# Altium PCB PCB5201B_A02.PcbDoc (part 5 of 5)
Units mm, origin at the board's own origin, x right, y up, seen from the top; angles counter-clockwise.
Board outline 115 x 60 mm, 6 copper layers (Top Layer, GND Layer 2, Signal Layer 3, Signal Layer 4, VCC Layer 5, Bottom Layer), stack 1.555 mm thick; 355 components, 250 nets, 1223 pads, 1070 vias.
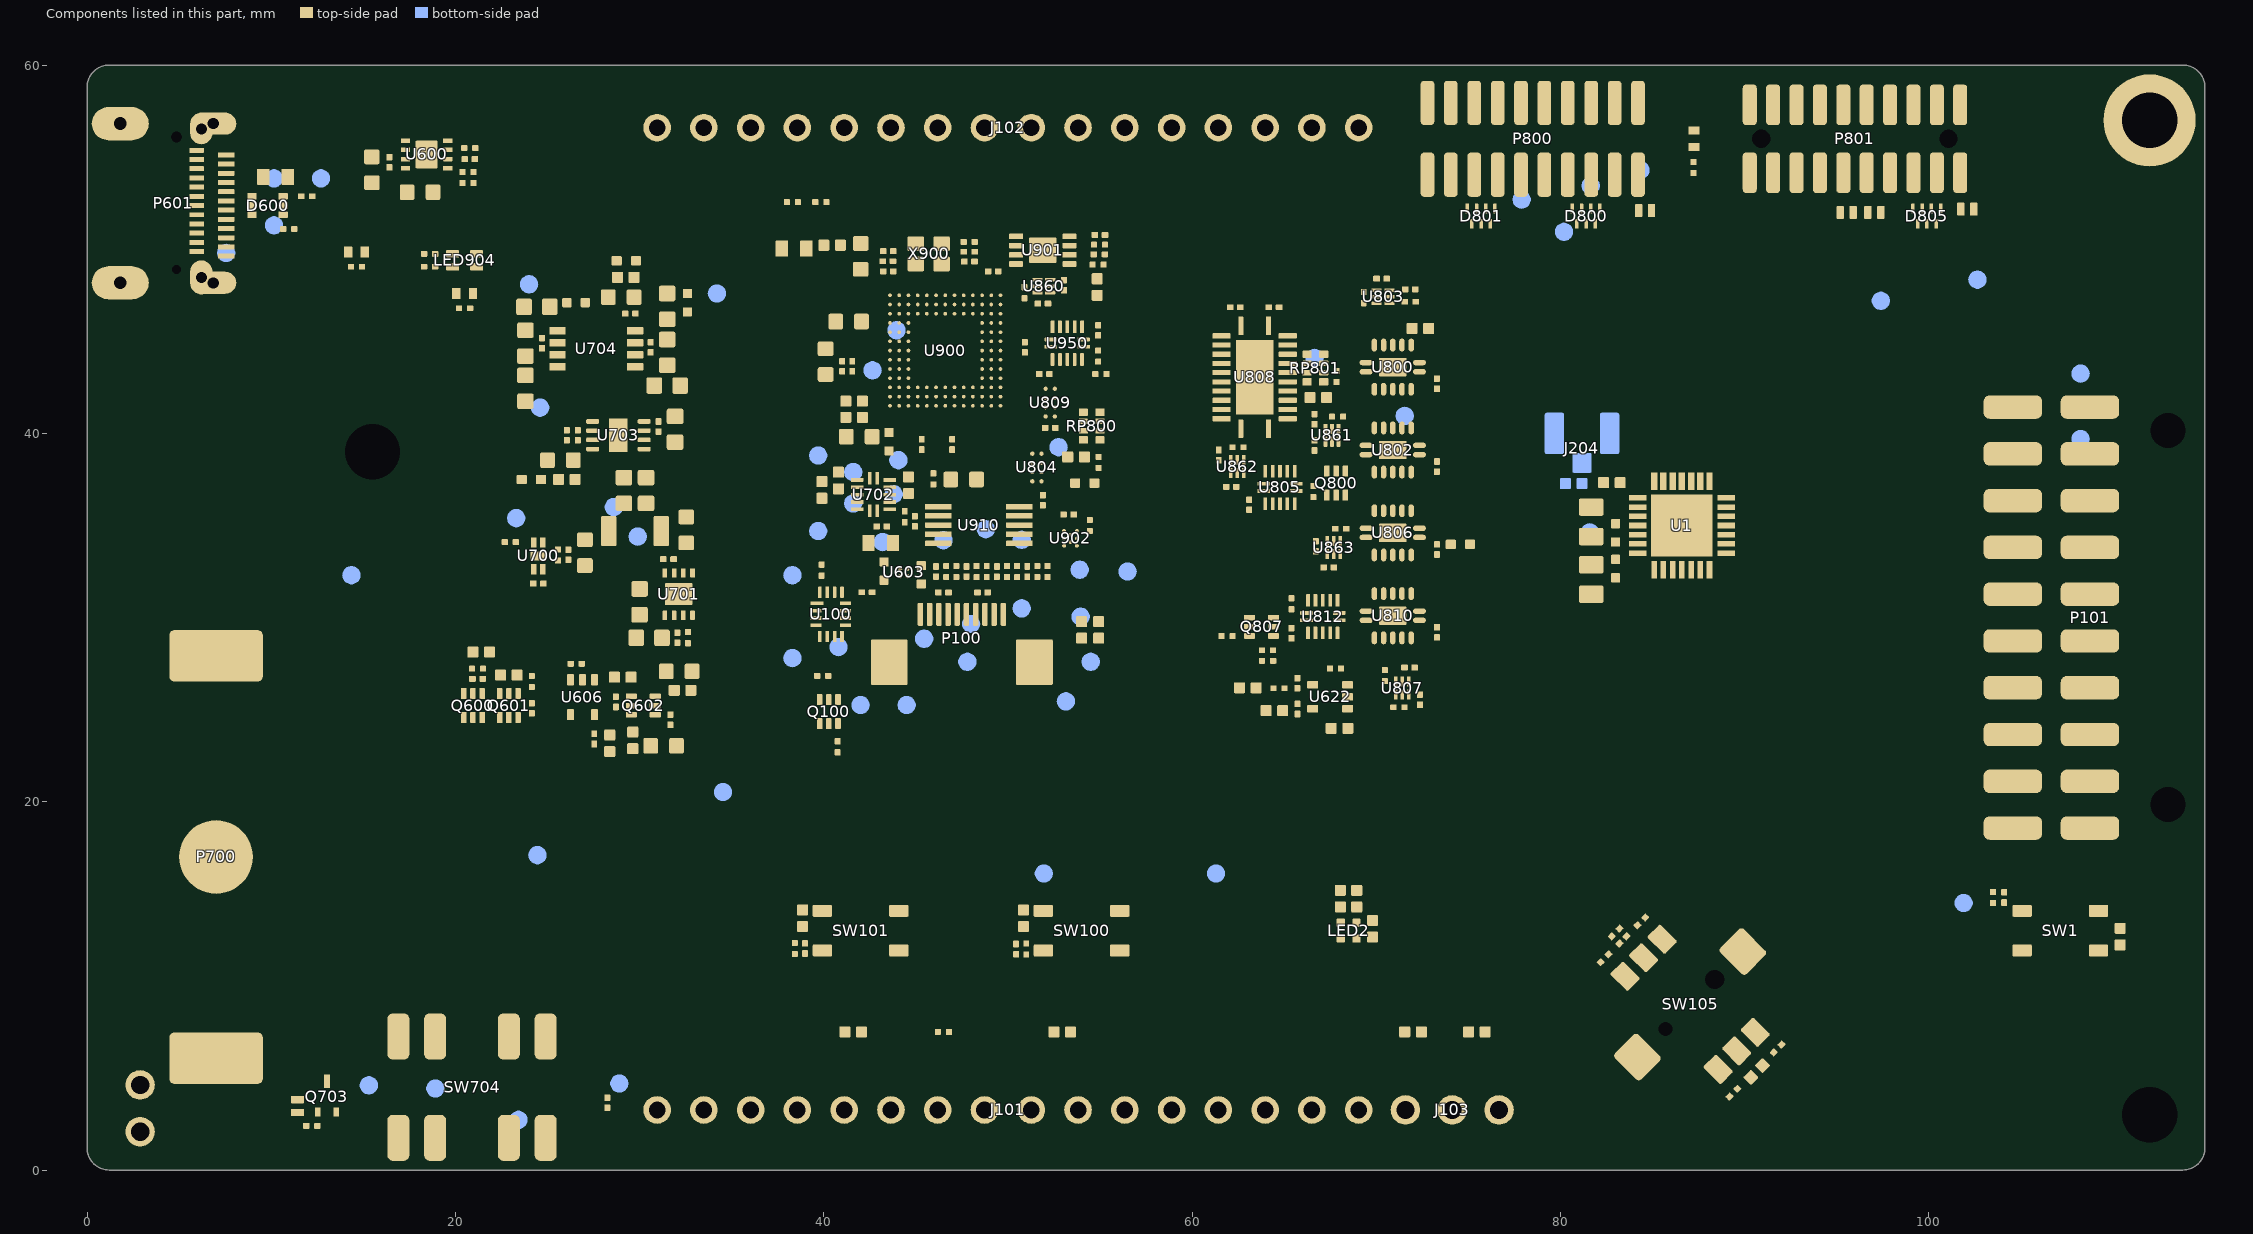
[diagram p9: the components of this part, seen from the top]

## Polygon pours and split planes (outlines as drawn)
VMCU on VCC Layer 5 "VMCU_L05_P027" (solid, remove dead copper, pour order 27): 77.925,39.7 78.35,40.125 101.725,40.125 102.45,40.85 102.45,59.275 103.175,60 115,60 115,0 21.05,0 21,0 20.275,0.725 20.275,6.3 20.525,6.55 29.025,6.55 29.55,7.075 29.55,23.225 30.05,23.725 77,23.725 77.925,24.65
3V3 on VCC Layer 5 "3V3_L05_P024" (solid, remove dead copper, pour order 24): 8.575,35.895 8.655,35.975 17.95,35.975 30.15,35.975 33.6,32.525 41.5,32.525 44.511,35.536 44.511,42.104 42.691,43.95 37.65,43.95 36.142,45.458 18.139,45.458 15.55,48.08 15.55,52.3 15.965,52.715 63.865,52.715 68.451,57.301 70.656,57.299 77.682,50.375 95.65,50.375 99.4,54.125 99.4,59.05 99.825,59.475 101.95,59.475 102.225,59.2 102.225,41.075 101.525,40.375 78.1,40.375 77.625,39.9 77.65,39.825 77.65,24.775 76.875,24 29.85,24 29.3,23.45 29.3,23.225 29.3,7.275 29.3,7.225 28.875,6.775 19.525,6.775 17.875,8.425 17.875,26.425 8.575,35.725
5V on VCC Layer 5 "5V_L05_P005" (solid, remove dead copper, pour order 5): 42.575,43.7 37.487,43.7 35.988,45.225 18.05,45.225 15.35,47.925 15.35,52.4 15.875,52.925 63.725,52.925 68.35,57.55 70.775,57.55 77.75,50.575 95.6,50.575 99.25,54.225 99.25,59.1 98.9,59.45 7.825,59.45 7.65,59.275 7.65,36.6 8.05,36.2 30.275,36.2 33.7,32.775 41.4,32.775 44.275,35.65 44.275,42
GND on VCC Layer 5 "VCC Layer 5-GND" (solid, remove dead copper, pour order 28): 0.5,0.5 19.25,0.5 19.5,0.75 19.5,5.775 17.1,8.175 17.1,26.175 7.1,36.175 7.1,59.5 0.95,59.5 0.5,59.05 0.5,35.4
GND on Top Layer "GND_L01_P021" (solid, remove dead copper, pour order 21): 0,0 0,60 125,60 125,0
USBC_VBUS on Top Layer "USBC_VBUS_L01_P020" (solid, remove dead copper, pour order 20): 9.85,55.125 9.85,53.575 8.825,53.575 8.4,54 8.4,54.725 9,55.325 9.717,55.325
5V on Top Layer "5V_L01_P019" (solid, remove dead copper, pour order 19): 10.6,53.525 10.6,55.075 11.075,55.55 11.925,55.55 12.275,55.2 12.275,53.65 12.25,53.65 12.125,53.525 10.675,53.525
5V on Top Layer "5V_L01_P018" (solid, remove dead copper, pour order 18): 14.375,54.625 13.975,55.025 13.975,56.175 14.325,56.525 16.375,56.525 16.8,56.1 16.8,55.225 16.45,54.875 15.725,54.875 15.725,54.7 15.65,54.625
3V3 on Top Layer "3V3_L01_P017" (solid, remove dead copper, pour order 17): 17.025,54.5 16.825,54.3 16.825,53.85 16.225,53.25 16.225,51.875 16.55,51.55 17.95,51.55 18.25,51.85 18.25,52.55 17.775,53.025 17.775,54.2 17.475,54.5
VMCU_R on Top Layer "VMCU_R_L01_P016" (solid, remove dead copper, pour order 16): 31.5,32.2 31.475,32.225 31.475,32.8 31.375,32.9 31.05,32.9 30.25,33.7 29.3,33.7 28.95,33.35 28.95,32.575 29.35,32.175 31.475,32.175 31.5,32.2 31.5,32.225
VMCU_R on Top Layer "VMCU_R_L01_P015" (solid, remove dead copper, pour order 15): 30.525,35.475 30.375,35.325 30.375,34.25 29.875,33.75 29.325,33.75 28.95,33.375 28.95,33.2 29.175,32.975 30.125,32.975 31.05,33.9 31.475,33.9 31.575,34 31.575,35.475
VMCU_S on Top Layer "VMCU_S_L01_P014" (solid, remove dead copper, pour order 14): 28.725,35.5 28.675,35.45 28.675,33.925 27.25,33.925 27.15,33.825 26.75,33.825 26.475,33.55 26.45,33.575 25.275,33.575 25.075,33.775 25.075,34.95 25.6,35.475 28.575,35.475 28.6,35.5
5V on Top Layer "5V_L01_P013" (solid, remove dead copper, pour order 13): 31.7,33.075 31.7,33.625 32.15,34.075 32.15,34.35 32.25,34.45 33.25,34.45 33.725,34.925 34.05,34.925 34.325,34.65 34.325,33.4 33.825,32.9 32.25,32.9 32.075,33.075
AEM_VMCU on Top Layer "AEM_VMCU_L01_P002" (solid, remove dead copper, pour order 2): 24.375,32.875 24.35,32.9 23.65,32.9 23.3,32.55 23.3,31.625 23.1,31.425 23.1,31 23.325,30.775 24.3,30.775 24.55,31.025 24.55,31.5 24.375,31.675
GND on Signal Layer 3 "GND_L03_P025" (solid, remove dead copper, pour order 25): 0,0 0,60 125,60 125,0
3V3 on Signal Layer 3 "3V3_L03_P022" (solid, remove dead copper, pour order 22): 18.15,51.675 18.525,52.05 18.525,54.175 17.7,55 17.7,56.85 17.225,57.325 16.3,57.325 15.925,56.95 15.925,55.125 16.525,54.525 16.525,51.775 16.625,51.675
GND on GND Layer 2 "GND_L02_P009" (solid, remove dead copper, pour order 9): 0,0 0,60 125,60 125,0
GND on Bottom Layer "GND_L06_P008" (solid, remove dead copper, pour order 8): 0,0 0,60 125,60 125,0
GND on Signal Layer 4 "GND_L04_P012" (solid, remove dead copper, pour order 12): 0,0 0,60 125,60 125,0

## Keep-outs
Bottom Layer:
  region: 12.7,54.35 cw(c12.7,53.85) 13.2,53.85 cw(c12.7,53.85) 12.7,53.35 cw(c12.7,53.85) 12.2,53.85 cw(c12.7,53.85)
  region: 32.691,5.802 ccw(c33.491,5.802) 33.491,5.002 ccw(c33.491,5.802) 34.291,5.802 ccw(c33.491,5.802) 33.491,6.602 ccw(c33.491,5.802)
  region: 35.231,5.802 ccw(c36.031,5.802) 36.031,5.002 ccw(c36.031,5.802) 36.831,5.802 ccw(c36.031,5.802) 36.031,6.602 ccw(c36.031,5.802)
  region: 37.771,5.802 ccw(c38.571,5.802) 38.571,5.002 ccw(c38.571,5.802) 39.371,5.802 ccw(c38.571,5.802) 38.571,6.602 ccw(c38.571,5.802)
  region: 40.311,5.802 ccw(c41.111,5.802) 41.111,5.002 ccw(c41.111,5.802) 41.911,5.802 ccw(c41.111,5.802) 41.111,6.602 ccw(c41.111,5.802)
  region: 42.851,5.802 ccw(c43.651,5.802) 43.651,5.002 ccw(c43.651,5.802) 44.451,5.802 ccw(c43.651,5.802) 43.651,6.602 ccw(c43.651,5.802)
  region: 45.391,5.802 ccw(c46.191,5.802) 46.191,5.002 ccw(c46.191,5.802) 46.991,5.802 ccw(c46.191,5.802) 46.191,6.602 ccw(c46.191,5.802)
  region: 47.931,5.802 ccw(c48.731,5.802) 48.731,5.002 ccw(c48.731,5.802) 49.531,5.802 ccw(c48.731,5.802) 48.731,6.602 ccw(c48.731,5.802)
  region: 50.471,5.802 ccw(c51.271,5.802) 51.271,5.002 ccw(c51.271,5.802) 52.071,5.802 ccw(c51.271,5.802) 51.271,6.602 ccw(c51.271,5.802)
  region: 53.011,5.802 ccw(c53.811,5.802) 53.811,5.002 ccw(c53.811,5.802) 54.611,5.802 ccw(c53.811,5.802) 53.811,6.602 ccw(c53.811,5.802)
  region: 55.551,5.802 ccw(c56.351,5.802) 56.351,5.002 ccw(c56.351,5.802) 57.151,5.802 ccw(c56.351,5.802) 56.351,6.602 ccw(c56.351,5.802)
  region: 58.091,5.802 ccw(c58.891,5.802) 58.891,5.002 ccw(c58.891,5.802) 59.691,5.802 ccw(c58.891,5.802) 58.891,6.602 ccw(c58.891,5.802)
  region: 60.631,5.802 ccw(c61.431,5.802) 61.431,5.002 ccw(c61.431,5.802) 62.231,5.802 ccw(c61.431,5.802) 61.431,6.602 ccw(c61.431,5.802)
  region: 63.171,5.802 ccw(c63.971,5.802) 63.971,5.002 ccw(c63.971,5.802) 64.771,5.802 ccw(c63.971,5.802) 63.971,6.602 ccw(c63.971,5.802)
  region: 65.711,5.802 ccw(c66.511,5.802) 66.511,5.002 ccw(c66.511,5.802) 67.311,5.802 ccw(c66.511,5.802) 66.511,6.602 ccw(c66.511,5.802)
  region: 68.251,5.802 ccw(c69.051,5.802) 69.051,5.002 ccw(c69.051,5.802) 69.851,5.802 ccw(c69.051,5.802) 69.051,6.602 ccw(c69.051,5.802)
  region: 30.151,5.802 ccw(c30.951,5.802) 30.951,5.002 ccw(c30.951,5.802) 31.751,5.802 ccw(c30.951,5.802) 30.951,6.602 ccw(c30.951,5.802)
  region: 30.151,3.262 ccw(c30.951,3.262) 30.951,2.462 ccw(c30.951,3.262) 31.751,3.262 ccw(c30.951,3.262) 30.951,4.062 ccw(c30.951,3.262)
  region: 30.151,3.262 ccw(c30.951,3.262) 30.951,2.462 ccw(c30.951,3.262) 31.751,3.262 ccw(c30.951,3.262) 30.951,4.062 ccw(c30.951,3.262)
  region: 32.691,3.262 ccw(c33.491,3.262) 33.491,2.462 ccw(c33.491,3.262) 34.291,3.262 ccw(c33.491,3.262) 33.491,4.062 ccw(c33.491,3.262)
  region: 35.231,3.262 ccw(c36.031,3.262) 36.031,2.462 ccw(c36.031,3.262) 36.831,3.262 ccw(c36.031,3.262) 36.031,4.062 ccw(c36.031,3.262)
  region: 37.771,3.262 ccw(c38.571,3.262) 38.571,2.462 ccw(c38.571,3.262) 39.371,3.262 ccw(c38.571,3.262) 38.571,4.062 ccw(c38.571,3.262)
  region: 40.311,3.262 ccw(c41.111,3.262) 41.111,2.462 ccw(c41.111,3.262) 41.911,3.262 ccw(c41.111,3.262) 41.111,4.062 ccw(c41.111,3.262)
  region: 42.851,3.262 ccw(c43.651,3.262) 43.651,2.462 ccw(c43.651,3.262) 44.451,3.262 ccw(c43.651,3.262) 43.651,4.062 ccw(c43.651,3.262)
  region: 45.391,3.262 ccw(c46.191,3.262) 46.191,2.462 ccw(c46.191,3.262) 46.991,3.262 ccw(c46.191,3.262) 46.191,4.062 ccw(c46.191,3.262)
  region: 47.881,3.287 ccw(c48.681,3.287) 48.681,2.487 ccw(c48.681,3.287) 49.481,3.287 ccw(c48.681,3.287) 48.681,4.087 ccw(c48.681,3.287)
  region: 50.471,3.262 ccw(c51.271,3.262) 51.271,2.462 ccw(c51.271,3.262) 52.071,3.262 ccw(c51.271,3.262) 51.271,4.062 ccw(c51.271,3.262)
  region: 53.011,3.262 ccw(c53.811,3.262) 53.811,2.462 ccw(c53.811,3.262) 54.611,3.262 ccw(c53.811,3.262) 53.811,4.062 ccw(c53.811,3.262)
  region: 55.551,3.262 ccw(c56.351,3.262) 56.351,2.462 ccw(c56.351,3.262) 57.151,3.262 ccw(c56.351,3.262) 56.351,4.062 ccw(c56.351,3.262)
  region: 58.091,3.262 ccw(c58.891,3.262) 58.891,2.462 ccw(c58.891,3.262) 59.691,3.262 ccw(c58.891,3.262) 58.891,4.062 ccw(c58.891,3.262)
  region: 60.631,3.262 ccw(c61.431,3.262) 61.431,2.462 ccw(c61.431,3.262) 62.231,3.262 ccw(c61.431,3.262) 61.431,4.062 ccw(c61.431,3.262)
  region: 63.171,3.262 ccw(c63.971,3.262) 63.971,2.462 ccw(c63.971,3.262) 64.771,3.262 ccw(c63.971,3.262) 63.971,4.062 ccw(c63.971,3.262)
  region: 65.711,3.262 ccw(c66.511,3.262) 66.511,2.462 ccw(c66.511,3.262) 67.311,3.262 ccw(c66.511,3.262) 66.511,4.062 ccw(c66.511,3.262)
  region: 68.251,3.262 ccw(c69.051,3.262) 69.051,2.462 ccw(c69.051,3.262) 69.851,3.262 ccw(c69.051,3.262) 69.051,4.062 ccw(c69.051,3.262)
  region: 32.691,56.602 ccw(c33.491,56.602) 33.491,55.802 ccw(c33.491,56.602) 34.291,56.602 ccw(c33.491,56.602) 33.491,57.402 ccw(c33.491,56.602)
  region: 35.231,56.602 ccw(c36.031,56.602) 36.031,55.802 ccw(c36.031,56.602) 36.831,56.602 ccw(c36.031,56.602) 36.031,57.402 ccw(c36.031,56.602)
  region: 37.771,56.602 ccw(c38.571,56.602) 38.571,55.802 ccw(c38.571,56.602) 39.371,56.602 ccw(c38.571,56.602) 38.571,57.402 ccw(c38.571,56.602)
  region: 40.311,56.602 ccw(c41.111,56.602) 41.111,55.802 ccw(c41.111,56.602) 41.911,56.602 ccw(c41.111,56.602) 41.111,57.402 ccw(c41.111,56.602)
  region: 42.851,56.602 ccw(c43.651,56.602) 43.651,55.802 ccw(c43.651,56.602) 44.451,56.602 ccw(c43.651,56.602) 43.651,57.402 ccw(c43.651,56.602)
  region: 45.391,56.602 ccw(c46.191,56.602) 46.191,55.802 ccw(c46.191,56.602) 46.991,56.602 ccw(c46.191,56.602) 46.191,57.402 ccw(c46.191,56.602)
  region: 47.931,56.602 ccw(c48.731,56.602) 48.731,55.802 ccw(c48.731,56.602) 49.531,56.602 ccw(c48.731,56.602) 48.731,57.402 ccw(c48.731,56.602)
  region: 50.471,56.602 ccw(c51.271,56.602) 51.271,55.802 ccw(c51.271,56.602) 52.071,56.602 ccw(c51.271,56.602) 51.271,57.402 ccw(c51.271,56.602)
  region: 53.011,56.602 ccw(c53.811,56.602) 53.811,55.802 ccw(c53.811,56.602) 54.611,56.602 ccw(c53.811,56.602) 53.811,57.402 ccw(c53.811,56.602)
  region: 55.551,56.602 ccw(c56.351,56.602) 56.351,55.802 ccw(c56.351,56.602) 57.151,56.602 ccw(c56.351,56.602) 56.351,57.402 ccw(c56.351,56.602)
  region: 58.091,56.602 ccw(c58.891,56.602) 58.891,55.802 ccw(c58.891,56.602) 59.691,56.602 ccw(c58.891,56.602) 58.891,57.402 ccw(c58.891,56.602)
  region: 60.631,56.602 ccw(c61.431,56.602) 61.431,55.802 ccw(c61.431,56.602) 62.231,56.602 ccw(c61.431,56.602) 61.431,57.402 ccw(c61.431,56.602)
  region: 63.171,56.602 ccw(c63.971,56.602) 63.971,55.802 ccw(c63.971,56.602) 64.771,56.602 ccw(c63.971,56.602) 63.971,57.402 ccw(c63.971,56.602)
  region: 65.711,56.602 ccw(c66.511,56.602) 66.511,55.802 ccw(c66.511,56.602) 67.311,56.602 ccw(c66.511,56.602) 66.511,57.402 ccw(c66.511,56.602)
  region: 68.251,56.602 ccw(c69.051,56.602) 69.051,55.802 ccw(c69.051,56.602) 69.851,56.602 ccw(c69.051,56.602) 69.051,57.402 ccw(c69.051,56.602)
  region: 30.151,56.602 ccw(c30.951,56.602) 30.951,55.802 ccw(c30.951,56.602) 31.751,56.602 ccw(c30.951,56.602) 30.951,57.402 ccw(c30.951,56.602)
  region: 30.151,54.062 ccw(c30.951,54.062) 30.951,53.262 ccw(c30.951,54.062) 31.751,54.062 ccw(c30.951,54.062) 30.951,54.862 ccw(c30.951,54.062)
  region: 30.151,54.062 ccw(c30.951,54.062) 30.951,53.262 ccw(c30.951,54.062) 31.751,54.062 ccw(c30.951,54.062) 30.951,54.862 ccw(c30.951,54.062)
  region: 32.691,54.062 ccw(c33.491,54.062) 33.491,53.262 ccw(c33.491,54.062) 34.291,54.062 ccw(c33.491,54.062) 33.491,54.862 ccw(c33.491,54.062)
  region: 35.231,54.062 ccw(c36.031,54.062) 36.031,53.262 ccw(c36.031,54.062) 36.831,54.062 ccw(c36.031,54.062) 36.031,54.862 ccw(c36.031,54.062)
  region: 37.771,54.062 ccw(c38.571,54.062) 38.571,53.262 ccw(c38.571,54.062) 39.371,54.062 ccw(c38.571,54.062) 38.571,54.862 ccw(c38.571,54.062)
  region: 40.311,54.062 ccw(c41.111,54.062) 41.111,53.262 ccw(c41.111,54.062) 41.911,54.062 ccw(c41.111,54.062) 41.111,54.862 ccw(c41.111,54.062)
  region: 42.851,54.062 ccw(c43.651,54.062) 43.651,53.262 ccw(c43.651,54.062) 44.451,54.062 ccw(c43.651,54.062) 43.651,54.862 ccw(c43.651,54.062)
  region: 45.391,54.062 ccw(c46.191,54.062) 46.191,53.262 ccw(c46.191,54.062) 46.991,54.062 ccw(c46.191,54.062) 46.191,54.862 ccw(c46.191,54.062)
  region: 47.931,54.062 ccw(c48.731,54.062) 48.731,53.262 ccw(c48.731,54.062) 49.531,54.062 ccw(c48.731,54.062) 48.731,54.862 ccw(c48.731,54.062)
  region: 50.471,54.062 ccw(c51.271,54.062) 51.271,53.262 ccw(c51.271,54.062) 52.071,54.062 ccw(c51.271,54.062) 51.271,54.862 ccw(c51.271,54.062)
  region: 53.011,54.062 ccw(c53.811,54.062) 53.811,53.262 ccw(c53.811,54.062) 54.611,54.062 ccw(c53.811,54.062) 53.811,54.862 ccw(c53.811,54.062)
  region: 55.551,54.062 ccw(c56.351,54.062) 56.351,53.262 ccw(c56.351,54.062) 57.151,54.062 ccw(c56.351,54.062) 56.351,54.862 ccw(c56.351,54.062)
  region: 58.091,54.062 ccw(c58.891,54.062) 58.891,53.262 ccw(c58.891,54.062) 59.691,54.062 ccw(c58.891,54.062) 58.891,54.862 ccw(c58.891,54.062)
  region: 60.631,54.062 ccw(c61.431,54.062) 61.431,53.262 ccw(c61.431,54.062) 62.231,54.062 ccw(c61.431,54.062) 61.431,54.862 ccw(c61.431,54.062)
  region: 63.171,54.062 ccw(c63.971,54.062) 63.971,53.262 ccw(c63.971,54.062) 64.771,54.062 ccw(c63.971,54.062) 63.971,54.862 ccw(c63.971,54.062)
  region: 65.711,54.062 ccw(c66.511,54.062) 66.511,53.262 ccw(c66.511,54.062) 67.311,54.062 ccw(c66.511,54.062) 66.511,54.862 ccw(c66.511,54.062)
  region: 68.251,54.062 ccw(c69.051,54.062) 69.051,53.262 ccw(c69.051,54.062) 69.851,54.062 ccw(c69.051,54.062) 69.051,54.862 ccw(c69.051,54.062)
  region: 45.391,54.062 ccw(c46.191,54.062) 46.191,53.262 ccw(c46.191,54.062) 46.991,54.062 ccw(c46.191,54.062) 46.191,54.862 ccw(c46.191,54.062)
  region: 42.851,54.062 ccw(c43.651,54.062) 43.651,53.262 ccw(c43.651,54.062) 44.451,54.062 ccw(c43.651,54.062) 43.651,54.862 ccw(c43.651,54.062)
  region: 40.311,54.062 ccw(c41.111,54.062) 41.111,53.262 ccw(c41.111,54.062) 41.911,54.062 ccw(c41.111,54.062) 41.111,54.862 ccw(c41.111,54.062)
  region: 37.771,54.062 ccw(c38.571,54.062) 38.571,53.262 ccw(c38.571,54.062) 39.371,54.062 ccw(c38.571,54.062) 38.571,54.862 ccw(c38.571,54.062)
  region: 35.231,54.062 ccw(c36.031,54.062) 36.031,53.262 ccw(c36.031,54.062) 36.831,54.062 ccw(c36.031,54.062) 36.031,54.862 ccw(c36.031,54.062)
  region: 32.691,54.062 ccw(c33.491,54.062) 33.491,53.262 ccw(c33.491,54.062) 34.291,54.062 ccw(c33.491,54.062) 33.491,54.862 ccw(c33.491,54.062)
  region: 30.151,54.062 ccw(c30.951,54.062) 30.951,53.262 ccw(c30.951,54.062) 31.751,54.062 ccw(c30.951,54.062) 30.951,54.862 ccw(c30.951,54.062)
  region: 30.151,54.062 ccw(c30.951,54.062) 30.951,53.262 ccw(c30.951,54.062) 31.751,54.062 ccw(c30.951,54.062) 30.951,54.862 ccw(c30.951,54.062)
  region: 30.151,56.602 ccw(c30.951,56.602) 30.951,55.802 ccw(c30.951,56.602) 31.751,56.602 ccw(c30.951,56.602) 30.951,57.402 ccw(c30.951,56.602)
  region: 45.391,56.602 ccw(c46.191,56.602) 46.191,55.802 ccw(c46.191,56.602) 46.991,56.602 ccw(c46.191,56.602) 46.191,57.402 ccw(c46.191,56.602)
  region: 42.851,56.602 ccw(c43.651,56.602) 43.651,55.802 ccw(c43.651,56.602) 44.451,56.602 ccw(c43.651,56.602) 43.651,57.402 ccw(c43.651,56.602)
  region: 40.311,56.602 ccw(c41.111,56.602) 41.111,55.802 ccw(c41.111,56.602) 41.911,56.602 ccw(c41.111,56.602) 41.111,57.402 ccw(c41.111,56.602)
  region: 37.771,56.602 ccw(c38.571,56.602) 38.571,55.802 ccw(c38.571,56.602) 39.371,56.602 ccw(c38.571,56.602) 38.571,57.402 ccw(c38.571,56.602)
  region: 35.231,56.602 ccw(c36.031,56.602) 36.031,55.802 ccw(c36.031,56.602) 36.831,56.602 ccw(c36.031,56.602) 36.031,57.402 ccw(c36.031,56.602)
  region: 32.691,56.602 ccw(c33.491,56.602) 33.491,55.802 ccw(c33.491,56.602) 34.291,56.602 ccw(c33.491,56.602) 33.491,57.402 ccw(c33.491,56.602)
  region: 68.251,3.262 ccw(c69.051,3.262) 69.051,2.462 ccw(c69.051,3.262) 69.851,3.262 ccw(c69.051,3.262) 69.051,4.062 ccw(c69.051,3.262)
  region: 65.711,3.262 ccw(c66.511,3.262) 66.511,2.462 ccw(c66.511,3.262) 67.311,3.262 ccw(c66.511,3.262) 66.511,4.062 ccw(c66.511,3.262)
  region: 60.631,3.262 ccw(c61.431,3.262) 61.431,2.462 ccw(c61.431,3.262) 62.231,3.262 ccw(c61.431,3.262) 61.431,4.062 ccw(c61.431,3.262)
  region: 58.091,3.262 ccw(c58.891,3.262) 58.891,2.462 ccw(c58.891,3.262) 59.691,3.262 ccw(c58.891,3.262) 58.891,4.062 ccw(c58.891,3.262)
  region: 40.311,3.262 ccw(c41.111,3.262) 41.111,2.462 ccw(c41.111,3.262) 41.911,3.262 ccw(c41.111,3.262) 41.111,4.062 ccw(c41.111,3.262)
  region: 37.771,3.262 ccw(c38.571,3.262) 38.571,2.462 ccw(c38.571,3.262) 39.371,3.262 ccw(c38.571,3.262) 38.571,4.062 ccw(c38.571,3.262)
  region: 35.231,3.262 ccw(c36.031,3.262) 36.031,2.462 ccw(c36.031,3.262) 36.831,3.262 ccw(c36.031,3.262) 36.031,4.062 ccw(c36.031,3.262)
  region: 32.691,3.262 ccw(c33.491,3.262) 33.491,2.462 ccw(c33.491,3.262) 34.291,3.262 ccw(c33.491,3.262) 33.491,4.062 ccw(c33.491,3.262)
  region: 30.151,3.262 ccw(c30.951,3.262) 30.951,2.462 ccw(c30.951,3.262) 31.751,3.262 ccw(c30.951,3.262) 30.951,4.062 ccw(c30.951,3.262)
  region: 30.151,3.262 ccw(c30.951,3.262) 30.951,2.462 ccw(c30.951,3.262) 31.751,3.262 ccw(c30.951,3.262) 30.951,4.062 ccw(c30.951,3.262)
  region: 30.151,5.802 ccw(c30.951,5.802) 30.951,5.002 ccw(c30.951,5.802) 31.751,5.802 ccw(c30.951,5.802) 30.951,6.602 ccw(c30.951,5.802)
  region: 68.251,5.802 ccw(c69.051,5.802) 69.051,5.002 ccw(c69.051,5.802) 69.851,5.802 ccw(c69.051,5.802) 69.051,6.602 ccw(c69.051,5.802)
  region: 65.711,5.802 ccw(c66.511,5.802) 66.511,5.002 ccw(c66.511,5.802) 67.311,5.802 ccw(c66.511,5.802) 66.511,6.602 ccw(c66.511,5.802)
  region: 63.171,5.802 ccw(c63.971,5.802) 63.971,5.002 ccw(c63.971,5.802) 64.771,5.802 ccw(c63.971,5.802) 63.971,6.602 ccw(c63.971,5.802)
  region: 60.631,5.802 ccw(c61.431,5.802) 61.431,5.002 ccw(c61.431,5.802) 62.231,5.802 ccw(c61.431,5.802) 61.431,6.602 ccw(c61.431,5.802)
  region: 58.091,5.802 ccw(c58.891,5.802) 58.891,5.002 ccw(c58.891,5.802) 59.691,5.802 ccw(c58.891,5.802) 58.891,6.602 ccw(c58.891,5.802)
  region: 40.311,5.802 ccw(c41.111,5.802) 41.111,5.002 ccw(c41.111,5.802) 41.911,5.802 ccw(c41.111,5.802) 41.111,6.602 ccw(c41.111,5.802)
  region: 37.771,5.802 ccw(c38.571,5.802) 38.571,5.002 ccw(c38.571,5.802) 39.371,5.802 ccw(c38.571,5.802) 38.571,6.602 ccw(c38.571,5.802)
  region: 35.231,5.802 ccw(c36.031,5.802) 36.031,5.002 ccw(c36.031,5.802) 36.831,5.802 ccw(c36.031,5.802) 36.031,6.602 ccw(c36.031,5.802)
  region: 32.691,5.802 ccw(c33.491,5.802) 33.491,5.002 ccw(c33.491,5.802) 34.291,5.802 ccw(c33.491,5.802) 33.491,6.602 ccw(c33.491,5.802)
  region: 103.5,19 cw(c103.5,18.5) 104,18.5 cw(c103.5,18.5) 103.5,18 cw(c103.5,18.5) 103,18.5 cw(c103.5,18.5)
  region: 108.25,40.2 cw(c108.25,39.699) 108.75,39.7 cw(c108.25,39.7) 108.25,39.2 cw(c108.25,39.7) 107.75,39.7 cw(c108.25,39.699)
  region: 108.25,43.748 cw(c108.25,43.248) 108.75,43.248 cw(c108.25,43.248) 108.25,42.748 cw(c108.25,43.248) 107.75,43.248 cw(c108.25,43.248)
  region: 107,54.2 cw(c107,53.7) 107.5,53.7 cw(c107,53.7) 107,53.2 cw(c107,53.7) 106.5,53.7 cw(c107,53.7)
  region: 105.4,52.498 cw(c105.4,51.998) 105.9,51.998 cw(c105.4,51.998) 105.4,51.498 cw(c105.4,51.998) 104.9,51.998 cw(c105.4,51.998)
  region: 104.45,54.2 cw(c104.45,53.7) 104.95,53.7 cw(c104.45,53.7) 104.45,53.2 cw(c104.45,53.7) 103.95,53.7 cw(c104.45,53.7)
  region: 103.399,52.498 cw(c103.399,51.998) 103.899,51.998 cw(c103.399,51.998) 103.399,51.498 cw(c103.399,51.998) 102.899,51.998 cw(c103.399,51.998)
  region: 102.649,48.848 cw(c102.649,48.348) 103.149,48.348 cw(c102.649,48.348) 102.649,47.848 cw(c102.649,48.348) 102.149,48.348 cw(c102.649,48.348)
  region: 97.399,47.7 cw(c97.399,47.2) 97.899,47.2 cw(c97.399,47.2) 97.399,46.7 cw(c97.399,47.2) 96.899,47.2 cw(c97.399,47.2)
  region: 92.525,52.432 cw(c92.525,51.932) 93.025,51.932 cw(c92.525,51.932) 92.525,51.432 cw(c92.525,51.932) 92.025,51.932 cw(c92.525,51.932)
  region: 93.541,54.21 cw(c93.541,53.71) 94.041,53.71 cw(c93.541,53.71) 93.541,53.21 cw(c93.541,53.71) 93.041,53.71 cw(c93.541,53.71)
  region: 90.493,52.432 cw(c90.493,51.932) 90.993,51.932 cw(c90.493,51.932) 90.493,51.432 cw(c90.493,51.932) 89.993,51.932 cw(c90.493,51.932)
  region: 88.461,52.432 cw(c88.461,51.932) 88.961,51.932 cw(c88.461,51.932) 88.461,51.432 cw(c88.461,51.932) 87.961,51.932 cw(c88.461,51.932)
  region: 89.477,54.21 cw(c89.477,53.71) 89.977,53.71 cw(c89.477,53.71) 89.477,53.21 cw(c89.477,53.71) 88.977,53.71 cw(c89.477,53.71)
  region: 87.466,54.206 cw(c87.467,53.706) 87.967,53.706 cw(c87.466,53.707) 87.466,53.206 cw(c87.466,53.706) 86.967,53.706 cw(c87.467,53.706)
  region: 84.349,54.799 cw(c84.349,54.299) 84.849,54.3 cw(c84.349,54.3) 84.349,53.799 cw(c84.349,54.299) 83.849,54.299 cw(c84.349,54.299)
  region: 85.4,52.198 cw(c85.4,51.698) 85.9,51.699 cw(c85.4,51.699) 85.4,51.199 cw(c85.4,51.698) 84.9,51.698 cw(c85.4,51.698)
  region: 93.449,42.798 cw(c93.45,42.298) 93.95,42.298 cw(c93.449,42.298) 93.449,41.798 cw(c93.449,42.298) 92.949,42.298 cw(c93.45,42.298)
  region: 86.15,40.05 cw(c86.15,39.55) 86.65,39.55 cw(c86.149,39.55) 86.149,39.05 cw(c86.149,39.55) 85.65,39.55 cw(c86.15,39.55)
  region: 81.649,53.949 cw(c81.649,53.449) 82.149,53.449 cw(c81.649,53.449) 81.649,52.949 cw(c81.649,53.449) 81.149,53.449 cw(c81.649,53.448)
  region: 77.9,53.199 cw(c77.9,52.699) 78.4,52.699 cw(c77.9,52.699) 77.9,52.199 cw(c77.9,52.699) 77.4,52.699 cw(c77.9,52.699)
  region: 80.201,51.449 cw(c80.201,50.949) 80.701,50.949 cw(c80.201,50.949) 80.201,50.449 cw(c80.201,50.949) 79.701,50.949 cw(c80.201,50.949)
  region: 77.399,48.498 cw(c77.399,47.998) 77.899,47.998 cw(c77.399,47.998) 77.399,47.498 cw(c77.399,47.998) 76.899,47.998 cw(c77.399,47.998)
  region: 75.4,48.498 cw(c75.4,47.998) 75.9,47.998 cw(c75.4,47.998) 75.4,47.498 cw(c75.4,47.998) 74.9,47.998 cw(c75.4,47.998)
  region: 73.399,48.498 cw(c73.399,47.998) 73.899,47.998 cw(c73.399,47.998) 73.399,47.498 cw(c73.399,47.998) 72.899,47.998 cw(c73.399,47.998)
  region: 77.399,46.298 cw(c77.399,45.798) 77.899,45.798 cw(c77.399,45.798) 77.399,45.298 cw(c77.399,45.798) 76.899,45.798 cw(c77.399,45.798)
  region: 75.4,46.298 cw(c75.4,45.798) 75.9,45.798 cw(c75.4,45.798) 75.4,45.298 cw(c75.4,45.798) 74.9,45.798 cw(c75.4,45.798)
  region: 73.399,46.298 cw(c73.399,45.798) 73.899,45.798 cw(c73.399,45.798) 73.399,45.298 cw(c73.399,45.798) 72.899,45.798 cw(c73.399,45.798)
  region: 71.4,46.298 cw(c71.4,45.798) 71.9,45.798 cw(c71.4,45.798) 71.4,45.298 cw(c71.4,45.798) 70.9,45.798 cw(c71.4,45.798)
  region: 73.399,43.598 cw(c73.399,43.098) 73.899,43.098 cw(c73.399,43.098) 73.399,42.598 cw(c73.399,43.098) 72.899,43.098 cw(c73.399,43.098)
  region: 71.55,41.449 cw(c71.55,40.949) 72.05,40.949 cw(c71.55,40.949) 71.55,40.449 cw(c71.55,40.949) 71.05,40.949 cw(c71.55,40.949)
  region: 66.65,44.599 cw(c66.65,44.099) 67.15,44.099 cw(c66.65,44.099) 66.65,43.599 cw(c66.65,44.099) 66.15,44.099 cw(c66.65,44.099)
  region: 94.199,12.348 cw(c94.199,11.848) 94.699,11.848 cw(c94.199,11.849) 94.199,11.348 cw(c94.199,11.848) 93.699,11.848 cw(c94.199,11.848)
  region: 96.8,11.8 cw(c96.8,11.3) 97.3,11.3 cw(c96.8,11.3) 96.8,10.8 cw(c96.8,11.3) 96.3,11.3 cw(c96.8,11.3)
  region: 93.249,9.948 cw(c93.249,9.448) 93.749,9.448 cw(c93.249,9.448) 93.249,8.948 cw(c93.249,9.448) 92.749,9.448 cw(c93.249,9.448)
  region: 96.5,9.148 cw(c96.5,8.648) 97,8.648 cw(c96.5,8.648) 96.5,8.148 cw(c96.5,8.648) 96,8.648 cw(c96.5,8.648)
  region: 95.7,6.55 cw(c95.7,6.05) 96.2,6.05 cw(c95.7,6.05) 95.7,5.55 cw(c95.7,6.05) 95.2,6.05 cw(c95.7,6.049)
  region: 93.249,7.398 cw(c93.249,6.898) 93.749,6.898 cw(c93.249,6.898) 93.249,6.398 cw(c93.249,6.898) 92.749,6.898 cw(c93.249,6.898)
  region: 81.499,10.949 cw(c81.499,10.449) 81.999,10.449 cw(c81.499,10.449) 81.499,9.949 cw(c81.499,10.449) 80.999,10.449 cw(c81.499,10.449)
  region: 77.249,10.949 cw(c77.249,10.449) 77.749,10.449 cw(c77.249,10.449) 77.249,9.949 cw(c77.249,10.449) 76.749,10.449 cw(c77.249,10.449)
  region: 72.949,10.949 cw(c72.949,10.449) 73.449,10.449 cw(c72.949,10.449) 72.949,9.949 cw(c72.949,10.449) 72.449,10.449 cw(c72.949,10.449)
  region: 74.1,6.748 cw(c74.1,6.248) 74.6,6.248 cw(c74.1,6.248) 74.1,5.748 cw(c74.1,6.248) 73.6,6.248 cw(c74.1,6.248)
  region: 54.674,41.624 cw(c54.674,41.124) 55.174,41.125 cw(c54.674,41.125) 54.674,40.625 cw(c54.674,41.124) 54.174,41.124 cw(c54.674,41.124)
  region: 52.749,39.75 cw(c52.749,39.25) 53.249,39.25 cw(c52.748,39.25) 52.748,38.75 cw(c52.748,39.25) 52.249,39.25 cw(c52.749,39.25)
  region: 50.75,34.723 cw(c50.75,34.223) 51.25,34.223 cw(c50.749,34.223) 50.75,33.723 cw(c50.75,34.223) 50.25,34.223 cw(c50.75,34.223)
  region: 53.899,33.098 cw(c53.899,32.598) 54.399,32.598 cw(c53.899,32.598) 53.899,32.098 cw(c53.899,32.598) 53.399,32.598 cw(c53.899,32.598)
  region: 50.75,31 cw(c50.75,30.5) 51.25,30.5 cw(c50.749,30.5) 50.75,30 cw(c50.75,30.5) 50.25,30.5 cw(c50.75,30.5)
  region: 53.95,30.55 cw(c53.95,30.05) 54.45,30.05 cw(c53.95,30.05) 53.95,29.55 cw(c53.95,30.05) 53.45,30.05 cw(c53.95,30.05)
  region: 54.499,28.099 cw(c54.499,27.599) 54.999,27.599 cw(c54.498,27.599) 54.499,27.099 cw(c54.499,27.599) 53.999,27.599 cw(c54.499,27.599)
  region: 51.799,28.099 cw(c51.799,27.599) 52.299,27.599 cw(c51.798,27.599) 51.799,27.099 cw(c51.799,27.599) 51.299,27.599 cw(c51.799,27.599)
  region: 53.15,25.95 cw(c53.15,25.45) 53.65,25.45 cw(c53.15,25.45) 53.15,24.95 cw(c53.15,25.45) 52.65,25.45 cw(c53.15,25.45)
  region: 47.999,30.149 cw(c47.999,29.649) 48.499,29.649 cw(c47.999,29.649) 47.999,29.149 cw(c47.999,29.649) 47.499,29.649 cw(c47.999,29.649)
  region: 45.449,29.349 cw(c45.449,28.849) 45.949,28.849 cw(c45.448,28.849) 45.449,28.349 cw(c45.449,28.849) 44.949,28.849 cw(c45.449,28.849)
  region: 47,25.749 cw(c47.001,25.249) 47.501,25.25 cw(c47,25.25) 47,24.75 cw(c47,25.249) 46.501,25.249 cw(c47.001,25.249)
  region: 43.249,28 cw(c43.249,27.5) 43.749,27.5 cw(c43.249,27.5) 43.249,27 cw(c43.249,27.5) 42.749,27.5 cw(c43.249,27.5)
  region: 44.499,25.749 cw(c44.499,25.249) 44.999,25.25 cw(c44.499,25.25) 44.499,24.75 cw(c44.499,25.249) 43.999,25.249 cw(c44.499,25.249)
  region: 41.999,25.749 cw(c41.999,25.249) 42.499,25.25 cw(c41.999,25.25) 41.999,24.75 cw(c41.999,25.249) 41.499,25.249 cw(c41.999,25.249)
  region: 61.301,16.598 cw(c61.301,16.098) 61.801,16.098 cw(c61.301,16.098) 61.301,15.598 cw(c61.301,16.098) 60.801,16.098 cw(c61.301,16.098)
  region: 51.951,16.598 cw(c51.951,16.098) 52.451,16.098 cw(c51.951,16.098) 51.951,15.598 cw(c51.951,16.098) 51.451,16.098 cw(c51.951,16.098)
  region: 34.524,21.025 cw(c34.524,20.525) 35.024,20.525 cw(c34.524,20.525) 34.524,20.025 cw(c34.524,20.525) 34.024,20.525 cw(c34.524,20.525)
  region: 24.45,17.599 cw(c24.45,17.099) 24.95,17.099 cw(c24.45,17.099) 24.45,16.599 cw(c24.45,17.099) 23.95,17.099 cw(c24.45,17.098)
  region: 15.649,26.448 cw(c15.649,25.948) 16.149,25.948 cw(c15.649,25.948) 15.649,25.448 cw(c15.649,25.948) 15.149,25.948 cw(c15.649,25.948)
  region: 12.05,26.448 cw(c12.05,25.948) 12.55,25.948 cw(c12.05,25.948) 12.05,25.448 cw(c12.05,25.948) 11.55,25.948 cw(c12.05,25.948)
  region: 12.025,29.773 cw(c12.025,29.273) 12.525,29.273 cw(c12.025,29.273) 12.025,28.773 cw(c12.025,29.273) 11.525,29.273 cw(c12.025,29.273)
  region: 9.475,29.798 cw(c9.475,29.298) 9.975,29.298 cw(c9.474,29.298) 9.475,28.798 cw(c9.475,29.298) 8.975,29.298 cw(c9.475,29.298)
  region: 14.349,32.798 cw(c14.349,32.298) 14.849,32.298 cw(c14.349,32.298) 14.349,31.798 cw(c14.349,32.298) 13.849,32.298 cw(c14.349,32.298)
  region: 10.399,32.249 cw(c10.399,31.749) 10.899,31.749 cw(c10.399,31.75) 10.399,31.249 cw(c10.399,31.749) 9.899,31.749 cw(c10.399,31.749)
  region: 10.399,34.899 cw(c10.399,34.399) 10.899,34.399 cw(c10.399,34.399) 10.399,33.899 cw(c10.399,34.399) 9.899,34.399 cw(c10.399,34.398)
  region: 18.446,49.044 cw(c18.446,48.544) 18.946,48.544 cw(c18.446,48.544) 18.446,48.044 cw(c18.446,48.544) 17.946,48.544 cw(c18.446,48.544)
  region: 15.906,50.314 cw(c15.906,49.814) 16.406,49.814 cw(c15.906,49.814) 15.906,49.314 cw(c15.906,49.814) 15.406,49.814 cw(c15.906,49.814)
  region: 18.446,51.584 cw(c18.446,51.084) 18.946,51.084 cw(c18.446,51.084) 18.446,50.584 cw(c18.446,51.084) 17.946,51.084 cw(c18.446,51.084)
  region: 15.906,52.854 cw(c15.906,52.354) 16.406,52.354 cw(c15.906,52.354) 15.906,51.854 cw(c15.906,52.354) 15.406,52.354 cw(c15.906,52.354)
  region: 18.446,54.124 cw(c18.446,53.624) 18.946,53.624 cw(c18.446,53.624) 18.446,53.124 cw(c18.446,53.624) 17.946,53.624 cw(c18.446,53.624)
  region: 15.906,55.394 cw(c15.906,54.894) 16.406,54.894 cw(c15.906,54.894) 15.906,54.394 cw(c15.906,54.894) 15.406,54.894 cw(c15.906,54.894)
  region: 10.15,54.35 cw(c10.15,53.85) 10.65,53.85 cw(c10.15,53.85) 10.15,53.35 cw(c10.15,53.85) 9.65,53.85 cw(c10.15,53.85)
  region: 10.15,51.8 cw(c10.15,51.3) 10.65,51.3 cw(c10.15,51.3) 10.15,50.8 cw(c10.15,51.3) 9.65,51.3 cw(c10.15,51.3)
  region: 7.549,50.299 cw(c7.549,49.799) 8.049,49.799 cw(c7.549,49.799) 7.549,49.299 cw(c7.549,49.799) 7.049,49.799 cw(c7.549,49.798)
  region: 24.6,41.899 cw(c24.6,41.399) 25.1,41.399 cw(c24.6,41.399) 24.6,40.899 cw(c24.6,41.399) 24.1,41.399 cw(c24.6,41.399)
  region: 36.249,37.548 cw(c36.249,37.048) 36.749,37.048 cw(c36.249,37.048) 36.249,36.548 cw(c36.249,37.048) 35.749,37.048 cw(c36.249,37.048)
  region: 38.999,37.548 cw(c39,37.048) 39.5,37.048 cw(c38.999,37.048) 38.999,36.548 cw(c38.999,37.048) 38.5,37.048 cw(c39,37.048)
  region: 41.6,38.399 cw(c41.6,37.899) 42.101,37.899 cw(c41.6,37.899) 41.6,37.399 cw(c41.6,37.899) 41.1,37.899 cw(c41.601,37.899)
  region: 44.049,39.049 cw(c44.049,38.549) 44.549,38.549 cw(c44.049,38.549) 44.049,38.049 cw(c44.049,38.549) 43.549,38.549 cw(c44.049,38.549)
  region: 42.649,43.923 cw(c42.65,43.423) 43.15,43.423 cw(c42.649,43.423) 42.649,42.923 cw(c42.649,43.423) 42.149,43.423 cw(c42.65,43.423)
  region: 43.95,46.1 cw(c43.95,45.6) 44.45,45.6 cw(c43.95,45.6) 43.95,45.1 cw(c43.95,45.6) 43.45,45.6 cw(c43.95,45.6)
  region: 18.446,46.504 cw(c18.446,46.004) 18.946,46.004 cw(c18.446,46.004) 18.446,45.504 cw(c18.446,46.004) 17.946,46.004 cw(c18.446,46.004)

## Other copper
Top Layer:
  pour cut-out: 17.275,3.2 17.3,3.175 18.525,3.175 18.525,3.125 18.5,3.1 17.275,3.1
  pour cut-out: 74.325,2.7 74.45,2.825 76.175,2.825 76.175,2.525 74.3,2.525 74.3,2.675 74.325,2.7 74.327,2.7 74.357,2.73 74.357,2.732 74.375,2.75
  pour cut-out: 68.5,45.425 67.825,45.975 68.375,47.275 68.675,47.275 68.675,45.4 68.525,45.4 68.5,45.425 68.5,45.427 68.47,45.457 68.468,45.457 68.45,45.475
  pour cut-out: 68.975,24.975 69.1,25.1 70.825,25.1 70.825,24.8 68.95,24.8 68.95,24.95 68.975,24.975 68.977,24.975 69.007,25.005 69.007,25.007 69.025,25.025
  pour cut-out: 66.6,24.35 66.725,24.225 66.725,23.475 66.425,23.475 66.025,24.475 66.575,24.375 66.6,24.35 66.6,24.348 66.63,24.318 66.632,24.318 66.65,24.3
  pour cut-out: 15.975,55.325 16.825,55.325 16.825,55 16.675,54.85 16,54.85 15.95,54.9
  pour cut-out: 30.725,23.75 30.85,23.875 31.6,23.875 31.6,23.575 30.7,23.575 30.7,23.725 30.725,23.75 30.727,23.75 30.757,23.78 30.757,23.782 30.775,23.8
  pour cut-out: 67.05,23.025 67.175,23.15 68.9,23.15 68.9,22.85 67.025,22.85 67.025,23 67.05,23.025 67.052,23.025 67.082,23.055 67.082,23.057 67.1,23.075
  pour cut-out: 64.5,31.05 64.625,31.175 65.375,31.175 65.375,30.875 64.475,30.875 64.475,31.025 64.5,31.05 64.502,31.05 64.532,31.08 64.532,31.082 64.55,31.1
  pour cut-out: 65.15,31.625 65.275,31.75 66.025,31.75 66.025,31.45 65.125,31.45 65.125,31.6 65.15,31.625 65.152,31.625 65.182,31.655 65.182,31.657 65.2,31.675
  pour cut-out: 63.35,30.15 63.475,30.275 64.225,30.275 64.225,29.975 63.325,29.975 63.325,30.125 63.35,30.15 63.352,30.15 63.382,30.18 63.382,30.182 63.4,30.2
  pour cut-out: 64,27.15 64.125,27.275 64.875,27.275 64.875,26.975 63.975,26.975 63.975,27.125 64,27.15 64.002,27.15 64.032,27.18 64.032,27.182 64.05,27.2
  pour cut-out: 65.475,35.025 65.6,35.15 66.35,35.15 66.35,34.325 65.775,34.1 65.275,35.15 65.475,35.025 65.477,35.025 65.507,35.055 65.507,35.057 65.525,35.075
  pour cut-out: 83.55,35.125 83.675,35 83.675,34.25 83.375,34.25 83.375,35.15 83.525,35.15 83.55,35.125 83.55,35.123 83.58,35.093 83.582,35.093 83.6,35.075
  pour cut-out: 80.6,34.075 80.725,33.95 80.725,33.2 80.425,33.2 80.425,34.1 80.575,34.1 80.6,34.075 80.6,34.073 80.63,34.043 80.632,34.043 80.65,34.025
  pour cut-out: 31.1,32.625 31.1,33.025 31.4,33.025 31.55,32.875 31.55,32.75 31.25,32.75 31.175,32.675
  pour cut-out: 32.025,33.625 31.95,33.55 31.95,33.475 32.1,33.325 32.175,33.325 32.175,33.625
  pour cut-out: 25.8,33.975 25.95,33.975 25.95,33.9 25.925,33.875 25.75,33.875 25.75,33.925
  pour cut-out: 27.575,34.125 27.8,34.125 27.8,33.875 27.775,33.85 27.75,33.875 27.6,33.875 27.6,34.1
  pour cut-out: 26.425,33.65 26.5,33.65 26.5,33.55 26.425,33.55
  pour cut-out: 26.35,33.975 26.525,33.975 26.525,33.9 26.475,33.85 26.375,33.85 26.375,33.95
  region net BC_I2C_EXP_SDA: 107.11,43.21 106.86,42.96 106.86,41.26 107.335,40.785 110.735,40.785 111.16,41.21 111.16,43.085 111.035,43.21
  region net 3V3: 102.16,43.21 101.55,42.6 101.55,41.475 102.24,40.785 105.985,40.785 106.175,40.975 106.175,42.75 105.715,43.21
  region net GND: 107.175,19.5 106.9,19.225 106.9,17.445 107.56,16.785 110.96,16.785 111.385,17.21 111.385,19.085 110.97,19.5
  region net VMCU: 102.175,19.2 101.925,18.95 101.925,17.25 102.4,16.775 105.8,16.775 106.225,17.2 106.225,19.075 106.1,19.2
  pour cut-out: 61.65,36.025 61.425,36.025 60.925,35.525 60.85,35.6 60.85,35.7 61,35.7 61.475,36.175
  pour cut-out: 41.075,46.95 41.125,46.9 41.125,46.5 41.55,46.5 41.6,46.55 41.425,46.725 41.425,47.1
  pour cut-out: 41.25,48.1 41.225,48.075 41.225,47.6 41.525,47.6 41.475,47.65 41.475,48.15 41.35,48.15 41.325,48.125
  pour cut-out: 40.05,40.075 40.05,40.175 40.55,40.675 40.5,40.725 40.225,40.725 40.225,40.575 39.85,40.2
  pour cut-out: 30.125,48.15 31.125,48.15 31.125,48.125 31.1,48.1 30.15,48.1 30.15,48.15 30.125,48.175
  pour cut-out: 26.175,46.725 26.075,46.625 26.075,45.85 25.9,45.85 25.875,45.875 25.975,45.975 25.975,46.725 26.05,46.725 26.075,46.75
  pour cut-out: 9.625,55.525 10.875,55.525 10.85,55.5 10.85,55.45 9.625,55.45 9.6,55.475
  pour cut-out: 23.95,32.4 23.95,32.05 24.1,32.05 24.1,32.4
  pour cut-out: 21.7,27.266 22.2,27.266 22.2,26.1 21.7,26.1
  region net N17481376: 10.542,26.275 10.542,29.5 3.462,29.5 3.462,26.275
  region net N17481376: 3.458,7.725 3.458,5.542 4.5,4.5 10.538,4.5 10.538,7.725
Signal Layer 3:
  pour cut-out: 92.85,30.378 92.85,28.7 92.85,28.65 91.6,28.65 91.6,30.222
  pour cut-out: 67.225,8.8 67.225,6.675 67.1,6.55 67.025,6.625 67.025,8.775
  pour cut-out: 65.375,9.525 65.375,7.4 65.25,7.275 65.175,7.35 65.175,9.5
  pour cut-out: 54.425,51.425 54.425,50.15 54.4,50.125 54.175,50.35 54.175,51.45 54.375,51.65
  pour cut-out: 43.187,51.262 43.15,51.3 43.15,54.55 43.325,54.45 43.325,51.125
  pour cut-out: 50.275,48.2 50.375,48.3 50.375,52.075 50.55,52.075 50.55,48.325
  pour cut-out: 78.675,27.606 78.675,24.85 78.55,24.725 78.475,24.8 78.475,27.581
  pour cut-out: 49.025,42.9 49.025,40.775 48.9,40.65 47.95,41.6 48.825,42.875
  pour cut-out: 65.75,44.45 65.75,42.325 65.625,42.2 65.55,42.275 65.55,44.425
  pour cut-out: 62.375,46.15 62.375,41.975 61.45,42.9 61.45,45.05
  pour cut-out: 89.9,30.778 89.9,29.1 89.9,29.05 88.65,29.05 88.65,30.622
  pour cut-out: 88.725,22.219 88.725,17.9 88.6,17.775 88.525,17.85 88.525,22.194
  pour cut-out: 56.537,10.2 55.756,8.072 49.32,8.625 50.681,10.2
  pour cut-out: 62.725,16.825 62.725,14.7 62.6,14.575 62.525,14.65 62.525,16.8
  pour cut-out: 65.3,16.675 65.3,14.55 65.1,13.475 65.1,14.5 65.1,16.65
  pour cut-out: 54,25.975 54.1,25.875 54.175,25.95 54.175,28.55 53.95,28.55 54,28.5 54,28.45
  pour cut-out: 39.7,32.95 39.7,32.025 39.65,31.975 39.65,32.95
  pour cut-out: 46.4,39.35 49.6,39.35 49.6,39.425 46.4,39.425 46.35,39.475
  pour cut-out: 43.8,37.675 45.075,37.675 45.075,37.775 45.05,37.8 43.8,37.8
  pour cut-out: 50.625,32.3 52.3,32.3 52.325,32.325 52.325,32.425 50.625,32.425 50.575,32.375
  pour cut-out: 60.525,32.9 60.525,31.675 60.45,31.75 60.45,32.9
  pour cut-out: 62.125,34.6 62.125,33.625 62.1,33.6 62.075,33.625 62.075,34.625
  pour cut-out: 61.15,40.225 61.15,38.5 61.1,38.45 61,38.55 61,40.325
  pour cut-out: 69.5,23.95 69.5,23.1 69.325,23.275 69.35,23.3 69.35,24
  pour cut-out: 50.525,43.625 50.525,42.35 50.5,42.325 50.275,42.55 50.275,43.65 50.475,43.85
  pour cut-out: 44.675,54.375 44.775,54.275 48.55,54.275 48.55,54.1 44.8,54.1
  pour cut-out: 68.725,45.725 68.7,45.7 68.7,43.875 68.6,43.875 68.5,43.975 68.575,44.05 68.575,45.725
  pour cut-out: 101.825,24.375 102.275,24.375 102.275,24.575 102.25,24.55 101.875,24.55 101.875,24.475 101.85,24.45
  pour cut-out: 72.625,39.95 73.325,39.95 73.325,40 73.25,40.075 72.7,40.075
  pour cut-out: 65.525,29.975 65.525,30.05 66.225,30.75 66.15,30.825 66.05,30.825 66.05,30.8 65.4,30.15
  pour cut-out: 71.9,34.2 71.95,34.5 72,30.975 72,31 71.95,31.05 71.95,33.7
  pour cut-out: 50.95,15.8 50.95,15.475 51.15,15.275 51.2,15.325 51.2,15.7
  pour cut-out: 42.825,21.5 42.825,20.55 42.65,20.375 42.65,21.6
  pour cut-out: 29.275,25.25 29.3,25.225 29.3,24.125 29.55,24.125 29.6,24.175 29.45,24.325 29.45,25.375
  pour cut-out: 52.025,29.85 52.025,28.875 52.05,28.9 52.1,28.9 52.1,29.775
  pour cut-out: 38.95,32.95 38.95,32.975 38.925,32.95 38.9,32.95
  pour cut-out: 33.8,36.175 33.8,35.05 33.825,35.025 33.85,35.05 33.925,35.05 33.925,36.125 33.875,36.175
  pour cut-out: 32.8,47.575 32.775,47.6 32.775,48.325 33.05,48.325 32.95,48.225 32.95,47.575
Signal Layer 4:
  pour cut-out: 66.021,33.927 63.971,33.927 64.146,34.102 66.096,34.102
  pour cut-out: 91.046,36.777 88.996,36.777 89.171,36.952 91.121,36.952
  pour cut-out: 85.171,26.652 83.121,26.652 83.296,26.827 85.246,26.827
  pour cut-out: 86.796,28.727 84.746,28.727 84.921,28.902 86.871,28.902
  pour cut-out: 93.671,32.202 91.621,32.202 91.796,32.377 93.746,32.377
  pour cut-out: 92.171,27.327 90.121,27.327 90.296,27.502 92.246,27.502
  pour cut-out: 89.75,24.225 87.7,24.225 87.875,24.4 89.825,24.4
  pour cut-out: 48.754,49.9 47.35,49.9 47.3,49.95 47.425,50.075 48.829,50.075
  pour cut-out: 49.2,44.65 48.525,44.65 48.475,44.7 48.6,44.825 49.275,44.825
  pour cut-out: 67.143,20.2 66.25,20.2 66.162,20.287 66.25,20.375 67.218,20.375
  pour cut-out: 80.786,23.512 77.625,23.325 80.424,23.151
  pour cut-out: 60.95,33.5 56,33.5 55.925,33.575 55.95,33.6 55.95,33.825 60.675,33.825 60.75,33.75
  pour cut-out: 54.825,51.5 54.825,50.15 54.65,50.15 54.6,50.2 54.75,50.35 54.75,51.5
  pour cut-out: 62.025,46.125 61.675,45.775 60.125,47.325 60.125,48.025
  pour cut-out: 71.843,25 70.625,25 70.575,25.05 70.7,25.175 71.918,25.175
  pour cut-out: 100.55,51.525 100.55,50.625 100.5,50.575 100.425,50.65 100.425,51.4 100.525,51.5
  pour cut-out: 85.225,49.95 83.775,49.95 83.775,51.1 85.225,51.1
  pour cut-out: 83.6,38.525 84.8,38.525 84.825,38.55 84.875,38.5 84.875,38.3 83.75,38.3 83.625,38.425
  pour cut-out: 70.225,48.475 70.25,48.5 71.025,48.5 71.025,48.25 70.975,48.2 70.825,48.35 70.125,48.35 70.125,48.5 70.2,48.575
  pour cut-out: 62.05,35.9 61.95,35.8 61.95,33.65 61.875,33.65 61.7,33.825 61.775,33.9 61.775,35.95
  pour cut-out: 41.55,47.475 42.925,47.475 43,47.4 42.975,47.375 41.65,47.375
  pour cut-out: 42.225,33.3 43.975,33.3 43.2,33.55 43.2,33.575 42.175,33.575 42.075,33.475
  pour cut-out: 46.525,27.05 47.725,27.05 47.85,27.175 47.775,27.25 46.475,27.25
VCC Layer 5:
  pour cut-out: 0.804,36.004 0.475,35.675 0.475,36.025
  pour cut-out: 0.8,36.125 0.45,36.475 0.45,36.125 0.675,36.125
  pour cut-out: 7.05,59.525 7.475,59.1 7.575,59.1 7.575,59.55 7.55,59.575 7.525,59.55 7.075,59.55
Bottom Layer:
  pour cut-out: 8.425,52.075 8.725,51.425 8.825,51.5 8.55,52.1
  pour cut-out: 69.435,43.966 70.75,44.575 70.013,42.763 69.56,43.216 69.385,43.391 68.86,43.391
  pour cut-out: 70.235,40.591 70.46,40.366 71.266,38.134 69.55,38.575 70.185,40.516
  pour cut-out: 67.86,45.116 68.085,44.891 68.438,43.913 67.985,44.366 67.81,44.541 67.81,45.041
  pour cut-out: 67.435,38.341 67.66,38.116 67.66,37.591 67.56,37.591 67.385,37.766 67.385,38.266
  pour cut-out: 48.75,29.55 48.875,29.425 49.35,29.425
  pour cut-out: 48.25,43.775 48.375,43.9 48.375,44.375
  pour cut-out: 45.975,43.5 46.1,43.375 46.775,43.375
  pour cut-out: 44.825,42.525 44.7,42.4 44.7,41.925
  pour cut-out: 55.45,36.975 55.3,36.975 55,36.675 55,36.875 55.15,36.875 55.325,37.05
  pour cut-out: 55.15,46.675 55.225,46.6 55.225,44.925 55.15,44.925 55.125,44.95 55.15,44.975
  pour cut-out: 42.975,26.925 42.975,25.375 42.95,25.35 43.025,25.35 43.025,26.875 43.075,26.925
  pour cut-out: 43.9,35.2 44,35.1 45.525,35.1 45.525,35.225 45.475,35.275 44,35.275
  pour cut-out: 48.425,33.6 48.4,33.575 48.4,33.525 47.8,33.525 47.725,33.6
  pour cut-out: 52.575,40.1 51.85,40.1 51.85,40.15 51.9,40.2 52.5,40.2
  pour cut-out: 49.625,42.5 49.625,40.925 49.65,40.9 49.7,40.95 49.8,40.95 49.8,42.3 49.775,42.325
  pour cut-out: 41.775,43.975 41.65,44.1 41.175,44.1
  pour cut-out: 12.5,53.2 12.25,52.95 12.25,52.9 12.05,53.1 12.3,53.35 12.425,53.35

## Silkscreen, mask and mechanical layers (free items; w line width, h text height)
Top Overlay:
  lines w0.2: 85.2,56 86.65,56 ; 87.85,56 89.3,56
  text "1" at 84.9,58.1 h1.5
  text "1" at 102.5,58.1 h1.5
  text "5V" at 30.375,55 h1.2 r315
  text "GND" at 32.425,55 h1.2 r315
  text "P0.0" at 35.325,55 h1.2 r315
  text "P0.1" at 37.925,55 h1.2 r315
  text "P0.2" at 40.325,55 h1.2 r315
  text "P0.3" at 43.025,55 h1.2 r315
  text "P0.4" at 45.625,55 h1.2 r315
  text "P0.5" at 48.025,55 h1.2 r315
  text "P0.6" at 50.625,55 h1.2 r315
  text "P0.7" at 53.125,55 h1.2 r315
  text "P1.0" at 55.625,55 h1.2 r315
  text "P1.2" at 60.725,55 h1.2 r315
  text "P1.3" at 63.275,55 h1.2 r315
  text "GND" at 65.375,55 h1.2 r315
  text "3V3" at 68.175,55 h1.2 r315
  text "P1.1" at 58.075,54.975 h1.2 r315
  text "2" at 102.5,53.1 h1.5
  text "2" at 84.9,52.9 h1.5
  text "SIMPLICITY" at 91.7,48.95 h1.6
  text "DEBUG" at 75.175,48.6 h1.6
  text "EXP" at 102.947,43.9 h2
  text "EFM8" at 79.605,43.07 h5.4
  text "20" at 103.947,42.3 h1.5
  text "19" at 107.847,42.3 h1.5
  text "Busy Bee" at 79.6,40.604 h3.2
  text "EFM8BB2" at 82.331,28.625 h2.1
  text "2" at 104.347,16.6 h1.5
  text "1" at 108.547,16.6 h1.5
  text "LED0" at 66.5,10.6 h2
  text "BTN1" at 40,9.6 h2
  text "BTN0" at 52,9.6 h2
  text "RESET" at 104.404,9.622 h2
  text "BAT" at 16.4,9 h2
  text "AEM" at 22,9 h2
  text "C2CK" at 72.25,6.5 h1.2 r315
  text "VMCU" at 28.95,6.45 h1.2 r315
  text "GND" at 31.95,5.875 h1.2 r315
  text "GND" at 65.15,5.75 h1.2 r315
  text "C2D" at 70.275,5.75 h1.2 r315
  text "RST" at 75.175,5.75 h1.2 r315
  text "P3.0" at 39.675,5.7 h1.2 r315
  text "P3.1" at 42.45,5.7 h1.2 r315
  text "P2.3" at 45.325,5.7 h1.2 r315
  text "P2.2" at 47.75,5.7 h1.2 r315
  text "P2.1" at 49.975,5.7 h1.2 r315
  text "P2.0" at 52.75,5.7 h1.2 r315
  text "P1.7" at 55.4,5.7 h1.2 r315
  text "P1.6" at 57.875,5.7 h1.2 r315
  text "P1.5" at 60.375,5.7 h1.2 r315
  text "P1.4" at 63,5.7 h1.2 r315
  text "3V3" at 67.825,5.625 h1.2 r315
  text "NC" at 35.024,5.345 h1.2 r315
  text "NC" at 37.483,5.345 h1.2 r315
Bottom Overlay:
  text "PCB5201B Rev A02" at 1.32,34.29 h1 r90
  text "SPI_CS" at 112.75,28.226 h1.7
  text "SPI_SCK" at 113.85,25.726 h1.7
  text "SPI_MISO" at 114.45,23.176 h1.7
  text "SPI_MOSI" at 114.375,21.126 h1.7
  text "BOARD INFO" at 19.8,15.775 h1.52
  text "BAT" at 7.4,4.1 h1.52
  text "GND" at 7.45,1.45 h1.52
Top Solder:
  the board outline again, w0.8
Bottom Solder:
  the board outline again, w0.8
Board Outline:
  lines w0.1: 0,1.2 ccw(c1.2,1.2) 1.2,0 ; 0,1.2 ccw(c1.2,1.2) 1.2,0 ; 0,1.2 0,58.8 ; 0,1.2 0,58.8 ; 0,58.8 cw(c1.2,58.8) 1.2,60 ; 0,58.8 cw(c1.2,58.8) 1.2,60 ; 1.2,0 113.8,0 ; 1.2,0 113.8,0 ; 1.2,60 113.8,60 ; 1.2,60 113.8,60 ; 113.8,0 ccw(c113.8,1.2) 115,1.2 ; 113.8,0 ccw(c113.8,1.2) 115,1.2 ; 113.8,60 cw(c113.8,58.8) 115,58.8 ; 113.8,60 cw(c113.8,58.8) 115,58.8 ; 115,1.2 115,58.8 ; 115,1.2 115,58.8
Route Tool Path:
  lines w0.1: 8.5,0 1.2,0 cw(c1.2,1.2) 0,1.2 0,58.8 cw(c1.2,58.8) 1.2,60 8.5,60 ; 15.5,0 56.5,0 ; 15.5,60 56.5,60 ; 63.5,0 94.5,0 ; 63.5,60 94.5,60 ; 101.5,0 113.8,0 ccw(c113.8,1.2) 115,1.2 115,58.8 ccw(c113.8,58.8) 113.8,60 101.5,60 ; -2.4,1.2 ccw(c1.2,1.2) 1.2,-2.4 ; -2.4,1.2 ccw(c1.2,1.2) 1.2,-2.4 ; -2.4,1.2 -2.4,58.8 ; -2.4,1.2 -2.4,58.8 ; -2.4,58.8 cw(c1.2,58.8) 1.2,62.4 ; 1.2,-2.4 8.5,-2.4 1.2,-2.4 ; 1.2,62.4 8.5,62.4 1.2,62.4 ; 113.8,-2.4 ccw(c113.8,1.2) 117.4,1.2 ; 113.8,-2.4 ccw(c113.8,1.2) 117.4,1.2 ; 113.8,-2.4 101.5,-2.4 113.8,-2.4 ; 113.8,62.4 cw(c113.8,58.8) 117.4,58.8 ; 113.8,62.4 cw(c113.8,58.8) 117.4,58.8 ; 113.8,62.4 101.5,62.4 113.8,62.4 ; 117.4,1.2 117.4,58.8 ; 117.4,1.2 117.4,58.8 ; 15.5,-2.4 56.5,-2.4 15.5,-2.4 ; 15.5,62.4 56.5,62.4 15.5,62.4 ; 63.5,-2.4 94.5,-2.4 63.5,-2.4 ; 63.5,62.4 94.5,62.4 63.5,62.4
  lines w2.4: 8.5,-1.2 1.2,-1.2 cw(c1.2,1.2) -1.2,1.2 -1.2,58.8 cw(c1.2,58.8) 1.2,61.2 8.5,61.2 ; 15.5,-1.2 56.5,-1.2 ; 15.5,61.2 56.5,61.2 ; 63.5,-1.2 94.5,-1.2 ; 63.5,61.2 94.5,61.2 ; 101.5,-1.2 113.8,-1.2 ccw(c113.8,1.2) 116.2,1.2 116.2,58.8 ccw(c113.8,58.8) 113.8,61.2 101.507,61.2
Top Component Center (Mech19):
  the board outline again, w0.1
Bottom Component Center:
  the board outline again, w0.1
